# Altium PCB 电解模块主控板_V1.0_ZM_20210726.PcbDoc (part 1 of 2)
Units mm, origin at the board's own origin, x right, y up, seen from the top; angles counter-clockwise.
Board outline 150.25 x 100.26 mm, 2 copper layers (Top Layer, Bottom Layer); 209 components, 149 nets, 716 pads, 1259 vias.
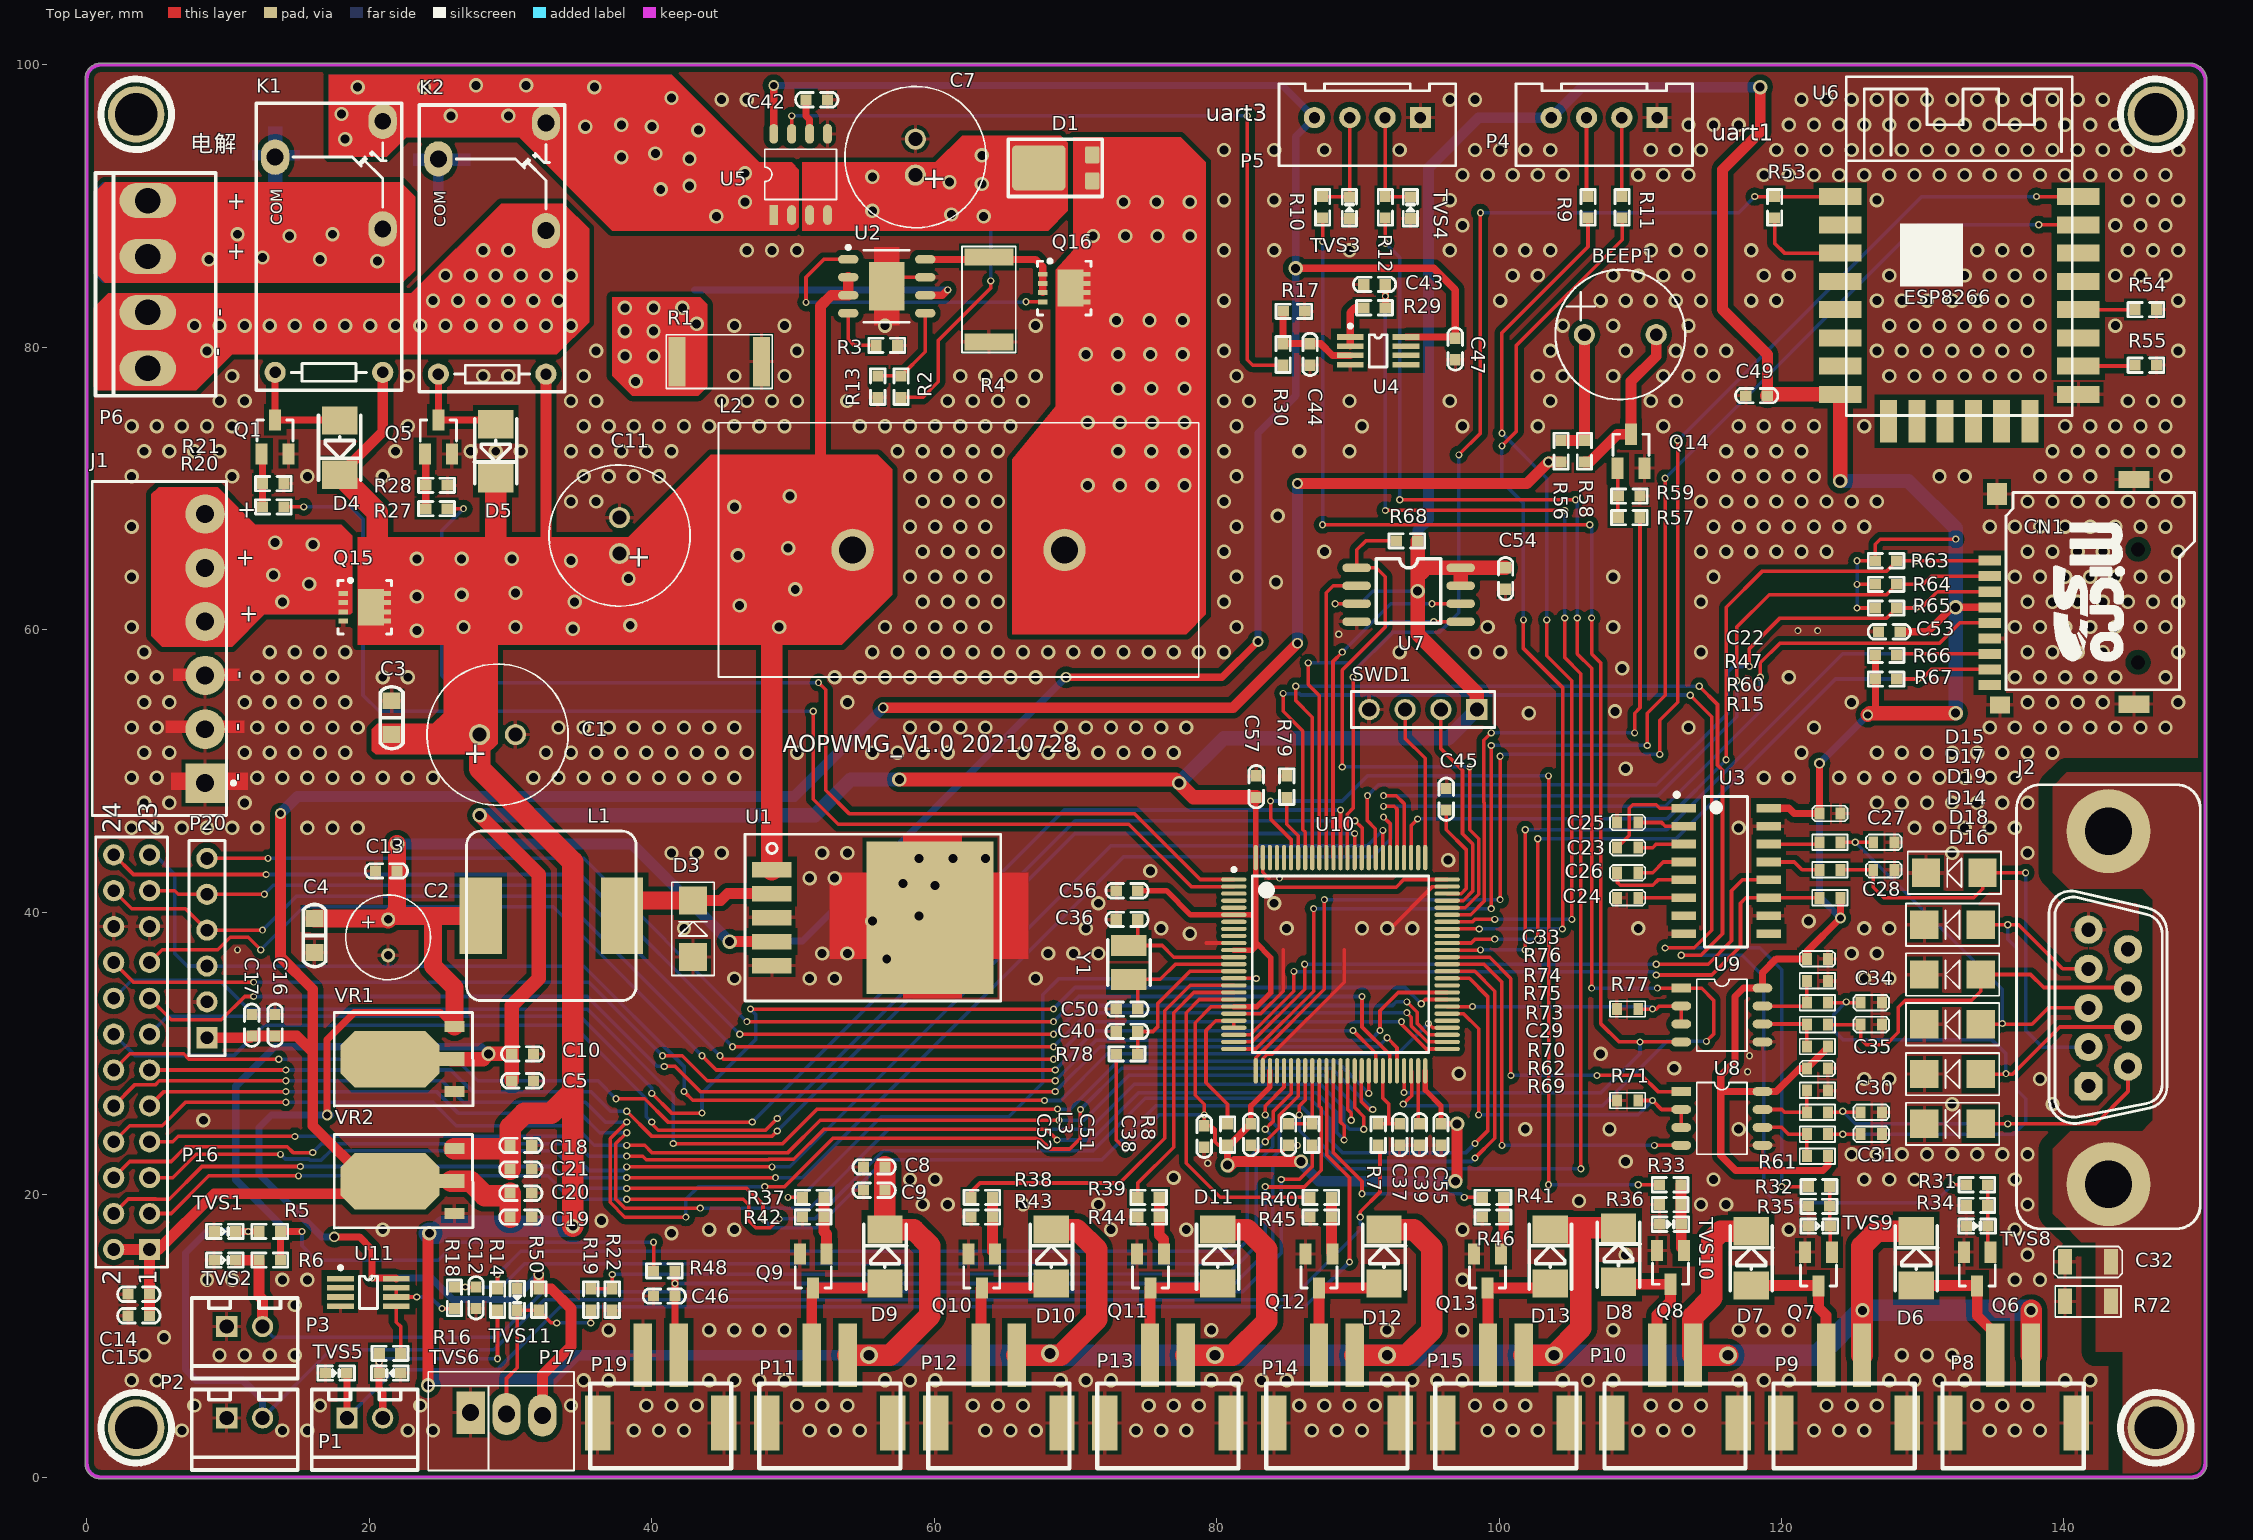
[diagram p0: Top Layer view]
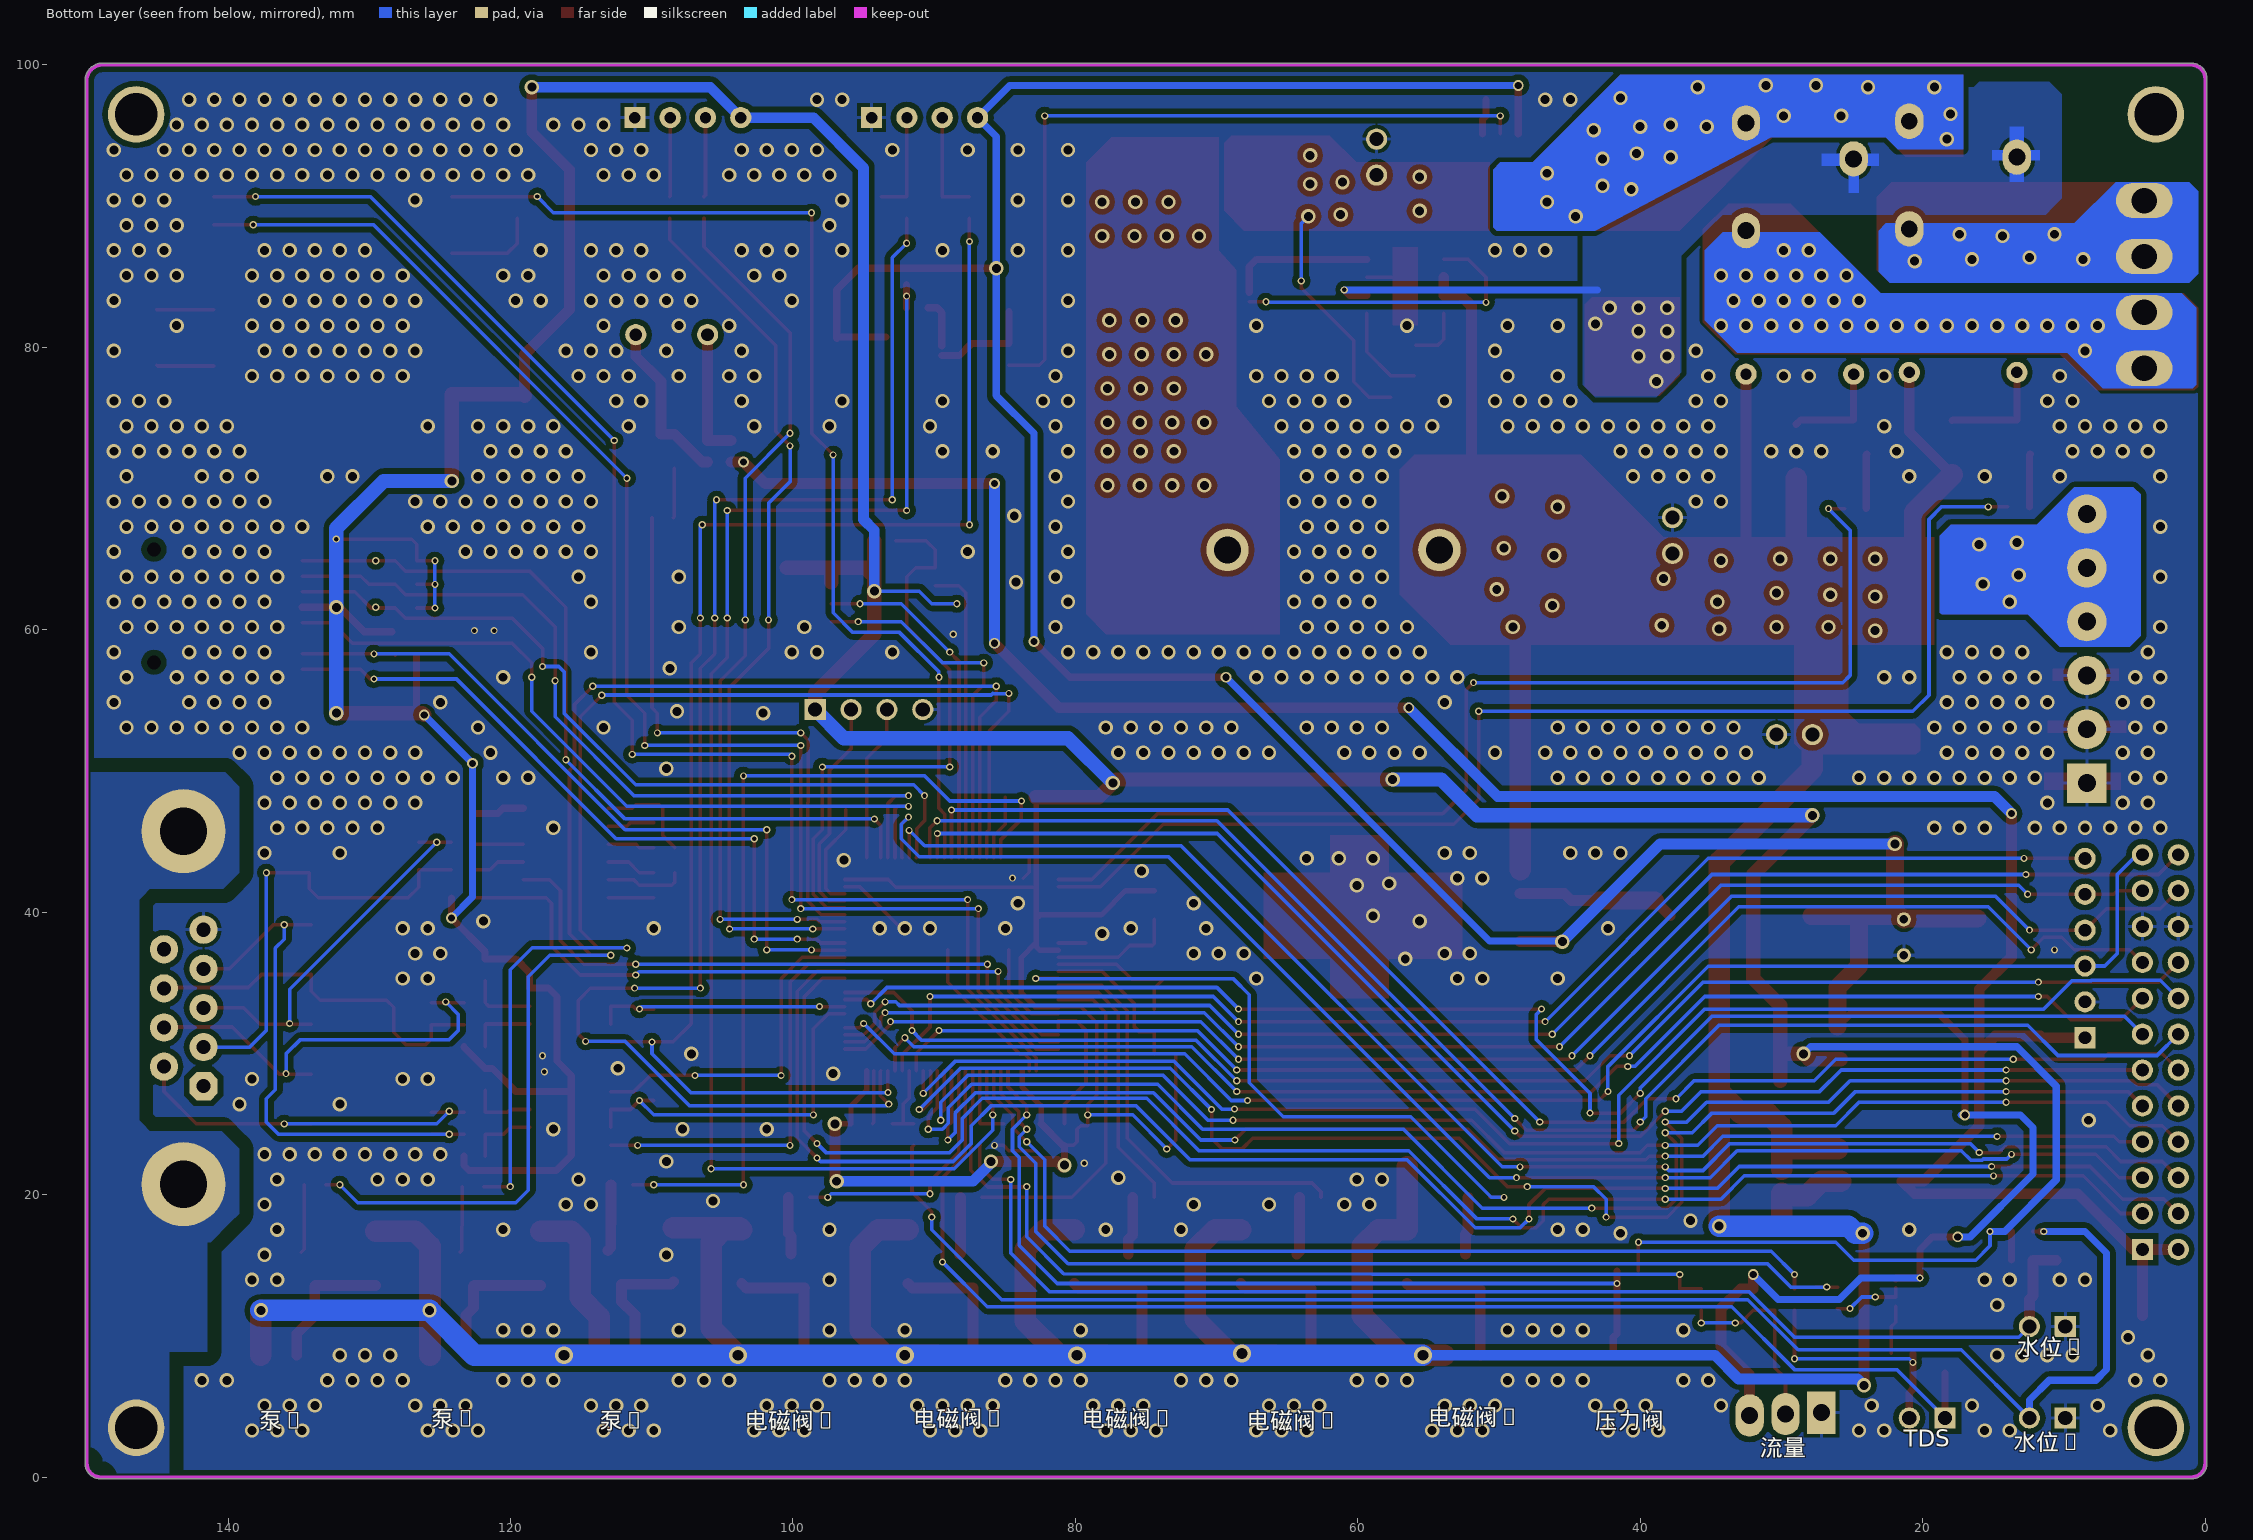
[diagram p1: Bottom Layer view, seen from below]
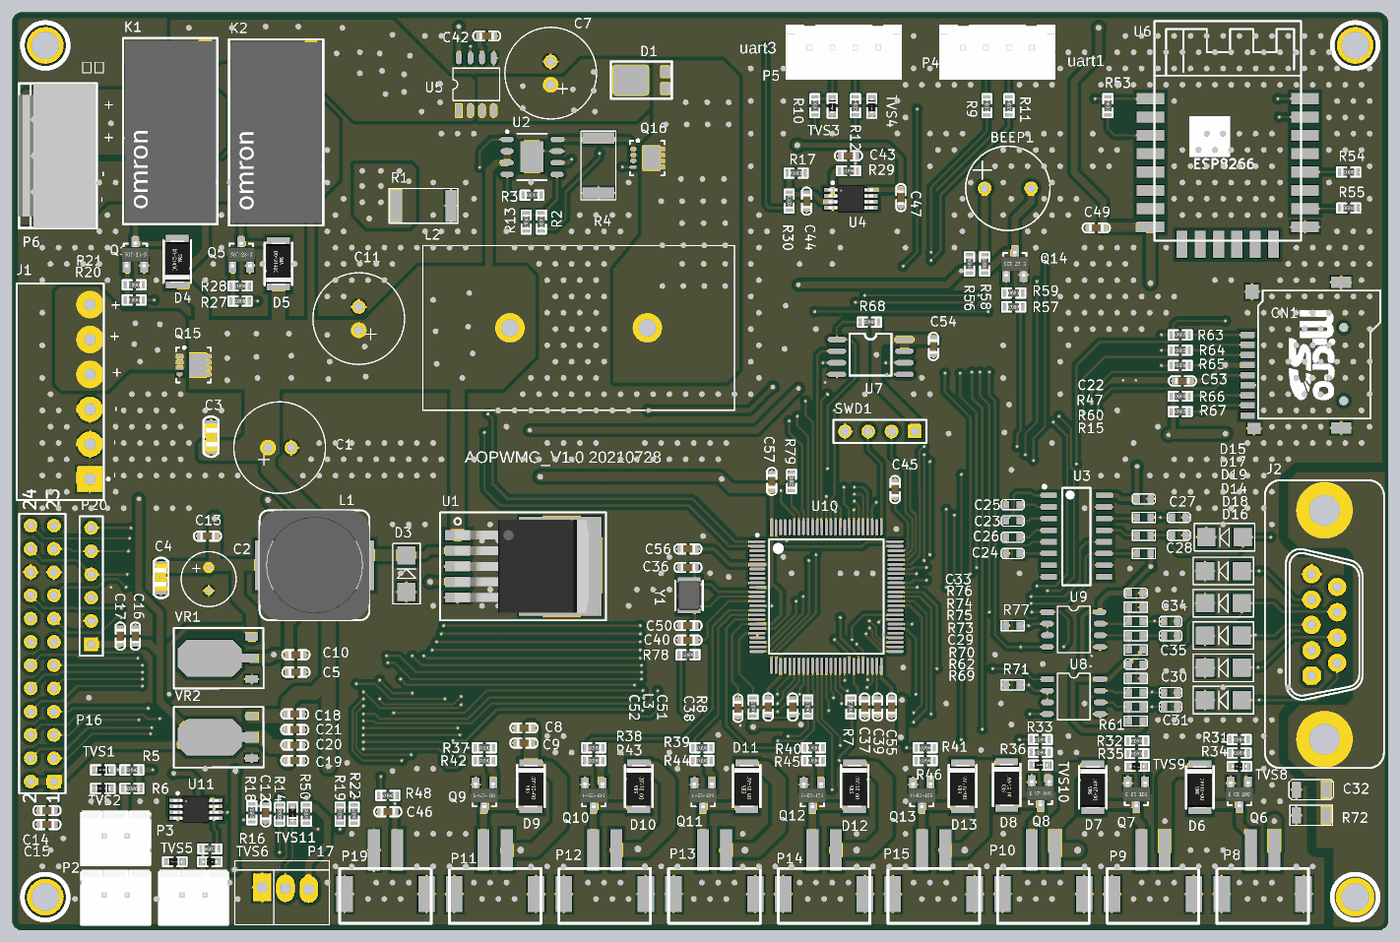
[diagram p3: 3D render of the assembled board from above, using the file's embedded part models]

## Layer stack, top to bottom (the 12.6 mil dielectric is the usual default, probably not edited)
Top Solder: solder mask 0.0102, Solder Resist, Dk 3.5
Top Layer: signal copper 0.0356
Dielectric1: dielectric 0.32, FR-4, Dk 4.8
Bottom Layer: signal copper 0.0356
Bottom Solder: solder mask 0.0102, Solder Resist, Dk 3.5

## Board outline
-0.127,1 ccw(c1,1) 1,-0.127 149,-0.127 ccw(c149,1) 150.127,1 150.127,99 ccw(c150,99) 150.126,99.016 ccw(c148.859,98.859) 148.709,100.127 1,100.127 ccw(c1,99) -0.127,99

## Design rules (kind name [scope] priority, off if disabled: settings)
Clearance Clearance_2 [InNet('NetC32_2')] p1: gap=0.152 except(1.016: Poly-Poly Poly-Region)
Clearance Clearance_1 [InPolygon] p2: gap=0.381
Clearance [All] p3: gap=0.152
NetAntennae [All] p1: netantennaetolerance=5.08
PolygonConnect PolygonConnect_2 [InNet('NetC32_2')] p1: connectstyle=Direct reliefconductorwidth=0.254 reliefentries=4 polygonreliefangle="90 Angle" airgapwidth=0.254
PolygonConnect PolygonConnect_1 [isvia] p2: connectstyle=Direct reliefconductorwidth=0.254 reliefentries=4 polygonreliefangle="90 Angle" airgapwidth=0.254
PolygonConnect [All] p3: connectstyle=Relief reliefconductorwidth=0.254 reliefentries=4 polygonreliefangle="90 Angle" airgapwidth=0.254
RoutingVias [All] p1: holewidth=0.305 width=0.61 viastyle="Through Hole" minholewidth=0.203 minwidth=0.203 maxholewidth=5.08 maxwidth=5.08
SilkToSolderMaskClearance [IsPad] p1: minsilkscreentomaskgap=0.051 clearancetoexposedcopper=TRUE
SolderMaskExpansion [All] p1: expansion=0.102
Width [All] p1: maxlimit=9.144 minlimit=0.254 preferedwidth=0.254
28 further rules are at their usual default settings.

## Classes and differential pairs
component class 02_Power: C1 C2 C3 C4 C5 C8 C9 C10 C13 C14 C15 C16 C17 C18 C19 C20 C21 D3 J1 L1 Q15 U1 VR1 VR2
component class 04_Sensor: C12 C37 C38 C47 P1 P2 P3 P17 R5 R6 R7 R8 R14 R16 R18 R19 R22 R50 TVS1 TVS2 TVS5 TVS6 TVS11 U11
component class com: C22 C23 C24 C25 C26 C27 C28 C29 C30 C31 C32 C33 C34 C35 D14 D15 D16 D17 D18 D19 J2 R15 R47 R60 R61 R62 R69 R70 R71 R72 R73 R74 R75 R76 R77 U3 U8 U9
component class 05_USART: P4 P5 R9 R10 R11 R12 TVS3 TVS4
component class cpu: C36 C39 C40 C45 C50 C51 C52 C55 C56 C57 L3 R78 R79 SWD1 U10 Y1
component class 07_EL_CON: C7 C11 C42 C43 C44 D1 D4 D5 K1 K2 L2 P6 Q1 Q5 Q16 R1 R2 R3 R4 R13 R17 R20 R21 R27 R28 R29 R30 U2 U4 U5
component class 08_Peripherals: C46 D6 D7 D8 D9 D10 D11 D12 D13 P8 P9 P10 P11 P12 P13 P14 P15 P19 Q6 Q7 Q8 Q9 Q10 Q11 Q12 Q13 R31 R32 R33 R34 R35 R36 R37 R38 R39 R40 R41 R42 R43 R44 R45 R46 R48 TVS8 TVS9 TVS10
component class 10_Wifi: C49 R53 R54 R55 U6
component class 11_Speak: BEEP1 BP1 Q14 R56 R57 R58 R59
component class 13_SPI_Flash: C54 R68 U7
component class 14_SD: C53 CN1 R63 R64 R65 R66 R67
component class 15_LCD: P16 P20

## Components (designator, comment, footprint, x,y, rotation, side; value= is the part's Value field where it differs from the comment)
BEEP1 "BEEP-9.5X5.5" BEEP-9.5X5.5 108.585,80.899 r0 top
C1 "1000uF/35V" 10*16 29.083,52.578 r180 top
C2 "100uF/35V" 6*8 21.336,38.227 r90 top
C3 "104 50V" SMD-0805C 21.59,53.778 r270 top
C4 "104 50V" SMD-0805C 16.129,38.354 r90 top
C5 "10uF 25V" SMD-0603C 30.861,28.067 r180 top
C7 "1000uF/35V" 10*16 58.674,93.472 r270 top
C8 "10uF 10V" SMD-0603C 55.753,21.971 r0 top
C9 "104 50V" SMD-0603C 55.753,20.32 r0 top
C10 "104 50V" SMD-0603C 30.861,29.972 r180 top
C11 "1000uF/35V" 10*16 37.719,66.675 r270 top
C12 "NC" SMD-0603C 27.559,12.7 r90 top
C13 "104 50V" SMD-0603C 21.209,42.926 r0 top
C14 "10uF 10V" SMD-0603C 3.683,12.954 r0 top
C15 "104 50V" SMD-0603C 3.683,11.43 r0 top
C16 "10uF 10V" SMD-0603C 13.335,32.004 r270 top
C17 "104 50V" SMD-0603C 11.684,32.004 r270 top
C18 "10uF 25V" SMD-0603C 30.734,23.495 r180 top
C19 "104 50V" SMD-0603C 30.734,18.415 r180 top
C20 "10uF 10V" SMD-0603C 30.734,20.108 r180 top
C21 "104 50V" SMD-0603C 30.734,21.802 r180 top
C22 "104 50V" 0603C 122.682,46.99 r0 top
C23 "104 50V" 0603C 108.355,44.577 r0 top
C24 "104 50V" 0603C 109.855,41.021 r180 top
C25 "104 50V" 0603C 109.855,46.355 r180 top
C26 "104 50V" 0603C 108.355,42.799 r0 top
C27 "220PF/16V" 0603C 126.492,44.958 r0 top
C28 "220PF/16V" 0603C 126.492,43.011 r0 top
C29 "104 50V" 0603C 121.793,28.942 r0 top
C30 "220PF/16V" 0603C 125.603,25.837 r0 top
C31 "220PF/16V" 0603C 125.603,24.285 r0 top
C32 "1NF/2KV" 1206C 140.081,15.24 r0 top
C33 "104 50V" 0603C 121.793,36.703 r0 top
C34 "220PF/16V" 0603C 125.603,33.599 r0 top
C35 "220PF/16V" 0603C 125.603,32.046 r0 top
C36 "12P/50V" SMD-0603C 73.66,39.497 r180 top
C37 "104 50V" SMD-0603C 92.964,24.257 r90 top
C38 "104 50V" SMD-0603C 85.09,24.257 r90 top
C39 "4.7uF/10V/NC" SMD-0603C 94.361,24.257 r90 top
C40 "1uF/10V" SMD-0603C 73.66,31.559 r0 top
C42 "104 50V" SMD-0603C 51.689,97.536 r0 top
C43 "NC" SMD-0603C 91.186,84.455 r0 top
C44 "104 50V" SMD-0603C 86.614,79.502 r270 top
C45 "4.7uF/10V/NC" SMD-0603C 96.266,48.006 r270 top
C46 "104 50V" SMD-0603C 40.894,12.827 r0 top
C47 "10uF 10V" SMD-0603C 96.901,79.883 r90 top
C49 "104 50V" SMD-0603C 118.237,76.581 r0 top
C50 "12P/50V" SMD-0603C 73.66,33.147 r180 top
C51 "104 50V" SMD-0603C 82.423,24.257 r90 top
C52 "104 50V" SMD-0603C 79.121,24.13 r90 top
C53 "104 50V" SMD-0603C 127.635,59.868 r180 top
C54 "104 50V" SMD-0603C 100.457,63.627 r270 top
C55 "104 50V" SMD-0603C 95.885,24.257 r90 top
C56 "104 50V" SMD-0603C 73.66,41.529 r0 top
C57 "104 50V" SMD-0603C 82.804,48.895 r270 top
CN1 "MicroSD Card" SD_Card_TF 134.747,64.897 r270 top
D1 "SB1545L" TO227 67.945,92.71 r90 top
D3 "SS34" SMA 42.926,36.83 r90 top
D4 "1N4007" DO-214-AC 17.907,72.898 r270 top
D5 "1N4007" DO-214-AC 28.956,72.644 r270 top
D6 "1N4007" DO-214-AC 129.54,15.494 r90 top
D7 "1N4007" DO-214-AC 117.856,15.494 r90 top
D8 "1N4007" DO-214-AC 108.458,15.748 r90 top
D9 "1N4007" DO-214-AC 56.515,15.621 r90 top
D10 "1N4007" DO-214-AC 68.294,15.621 r90 top
D11 "1N4007" DO-214-AC 80.073,15.621 r90 top
D12 "1N4007" DO-214-AC 91.853,15.621 r90 top
D13 "1N4007" DO-214-AC 103.632,15.621 r90 top
D14 "SMAJ18CA" SMA 134.112,32.067 r180 top
D15 "SMAJ18CA" SMA 134.239,42.799 r180 top
D16 "SMAJ6.5CA" SMA 134.112,25.019 r180 top
D17 "SMAJ6.5CA" SMA 134.112,39.116 r180 top
D18 "SMAJ6.5CA" SMA 134.112,28.543 r180 top
D19 "SMAJ6.5CA" SMA 134.112,35.592 r180 top
J1 "HEADER_6" DB2ERC-3P81-6P 8.382,49.149 r90 top
J2 "DB-9P-02" DIP-9 141.732,27.686 r90 top
K1 "G5Q-14-DC12" G5Q-14 17.145,87.122 r90 top
K2 "G5Q-14-DC12" G5Q-14 28.702,86.995 r90 top
L1 "33uH" CDRH-127 32.893,39.751 r180 top
L2 "33uH/15A" INDUCTOR_34*18 54.229,65.659 r0 top
L3 "MPZ1608D101BTA00" SMD-0603 80.772,24.257 r90 top
P1 "XH2.54 2P" SIP-2A 19.685,4.191 r0 top
P2 "XH2.54 2P" SIP-2A 11.176,4.191 r0 top
P3 "XH2.54 2P" SIP-2A 11.176,10.668 r0 top
P4 "1*4P" XH2.54-4A 107.442,96.266 r180 top
P5 "1*4P" XH2.54-4A 90.678,96.266 r180 top
P6 "SIP-4" VH-AW-3.96*4P 4.318,84.455 r90 top
P8 "SIP-2" XH-2.54-2P-LI 136.398,8.636 r180 top
P9 "SIP-2" XH-2.54-2P-LI 124.428,8.636 r180 top
P10 "SIP-2" XH-2.54-2P-LI 112.459,8.636 r180 top
P11 "SIP-2" XH-2.54-2P-LI 52.61,8.636 r180 top
P12 "SIP-2" XH-2.54-2P-LI 64.579,8.636 r180 top
P13 "SIP-2" XH-2.54-2P-LI 76.549,8.636 r180 top
P14 "SIP-2" XH-2.54-2P-LI 88.519,8.636 r180 top
P15 "SIP-2" XH-2.54-2P-LI 100.489,8.636 r180 top
P16 "Header 12X2" HDR2X12 4.445,16.129 r90 top
P17 "1*3P" 3X2.54MMZ2 27.178,4.572 r0 top
P19 "SIP-2" XH-2.54-2P-LI 40.64,8.636 r180 top
P20 "Header 6" HDR1X6 8.509,31.115 r90 top
Q1 "SS8050" SOT-23 13.335,73.66 r0 top
Q5 "SS8050" SOT-23 24.892,73.66 r0 top
Q6 "AO3400" SOT-23 133.858,14.732 r180 top
Q7 "AO3400" SOT-23 122.618,14.732 r180 top
Q8 "AO3400" SOT-23 112.141,14.859 r180 top
Q9 "SS8050" SOT-23 51.435,14.605 r180 top
Q10 "SS8050" SOT-23 63.373,14.605 r180 top
Q11 "SS8050" SOT-23 75.311,14.605 r180 top
Q12 "SS8050" SOT-23 87.249,14.605 r180 top
Q13 "SS8050" SOT-23 99.187,14.605 r180 top
Q14 "S8050" SOT-23 109.347,72.644 r0 top
Q15 "AON7426" DFN3*3-8 19.685,61.595 r270 top
Q16 "AON7506" DFN3*3-8 69.215,84.201 r270 top
R1 "0.03/1w" 2512R 41.783,78.994 r0 top
R2 "23K/1%" SMD-0603 57.658,77.216 r90 top
R3 "38.3K/1%" SMD-0603 56.642,80.137 r0 top
R4 "0.027/1%" 2512r 63.881,86.391 r270 top
R5 "10K" SMD-0603 12.954,17.399 r180 top
R6 "10K" SMD-0603 12.954,15.367 r180 top
R7 "10K" SMD-0603 91.44,24.257 r90 top
R8 "10K" SMD-0603 86.741,24.257 r90 top
R9 "10R" SMD-0603 106.299,89.916 r270 top
R10 "100R" SMD-0603 87.503,89.916 r270 top
R11 "10R" SMD-0603 108.712,89.916 r270 top
R12 "100R" SMD-0603 91.948,89.916 r270 top
R13 "1K/1%" SMD-0603 56.007,77.216 r270 top
R14 "510K" SMD-0603 29.083,12.573 r270 top
R15 "4.75K 1%" 0603R 124.182,41.021 r180 top
R16 "10K" SMD-0603 21.463,8.763 r0 top
R17 "10K" SMD-0603 85.471,82.55 r180 top
R18 "4.7K" SMD-0603 26.035,12.7 r270 top
R19 "10K" SMD-0603 35.687,12.573 r90 top
R20 "1K" SMD-0603 13.208,68.707 r180 top
R21 "47K" SMD-0603 13.208,70.358 r180 top
R22 "20K" SMD-0603 37.211,12.573 r90 top
R27 "1K" SMD-0603 24.765,68.58 r180 top
R28 "47K" SMD-0603 24.765,70.231 r180 top
R29 "100R" SMD-0603 91.186,82.804 r180 top
R30 "10K" SMD-0603 84.709,79.502 r270 top
R31 "100R" SMD-0603 133.833,20.701 r180 top
R32 "100R" SMD-0603 122.657,20.574 r180 top
R33 "100R" SMD-0603 112.116,20.701 r180 top
R34 "10K" SMD-0603 133.833,19.241 r180 top
R35 "10K" SMD-0603 122.657,19.177 r180 top
R36 "10K" SMD-0603 112.116,19.304 r180 top
R37 "1K" SMD-0603 51.435,19.812 r180 top
R38 "1K" SMD-0603 63.373,19.812 r180 top
R39 "1K" SMD-0603 75.184,19.812 r180 top
R40 "1K" SMD-0603 87.376,19.812 r180 top
R41 "1K" SMD-0603 99.568,19.812 r180 top
R42 "10K" SMD-0603 51.435,18.415 r180 top
R43 "10K" SMD-0603 63.373,18.415 r180 top
R44 "10K" SMD-0603 75.184,18.415 r180 top
R45 "10K" SMD-0603 87.376,18.415 r180 top
R46 "10K" SMD-0603 99.568,18.415 r180 top
R47 "22R 5%" 0603R 122.682,44.958 r0 top
R48 "10K" SMD-0603 40.894,14.605 r180 top
R50 "10K" SMD-0603 32.004,12.573 r270 top
R53 "1K" SMD-0603 119.507,89.916 r270 top
R54 "NC" SMD-0603 145.796,82.677 r180 top
R55 "1K" SMD-0603 145.796,78.74 r0 top
R56 "51R" SMD-0603 104.394,72.644 r270 top
R57 "4.7K" SMD-0603 109.22,67.945 r180 top
R58 "1K" SMD-0603 106.045,72.644 r90 top
R59 "47K" SMD-0603 109.22,69.469 r0 top
R60 "22R 5%" 0603R 122.682,43.011 r0 top
R61 "750R 5%" 0603R 121.793,22.733 r0 top
R62 "8.2R 5%" 0603R 121.793,25.837 r0 top
R63 "4.7K" SMD-0603 127.406,64.897 r0 top
R64 "4.7K" SMD-0603 127.406,63.221 r0 top
R65 "4.7K" SMD-0603 127.406,61.544 r0 top
R66 "4.7K" SMD-0603 127.406,58.191 r0 top
R67 "4.7K" SMD-0603 127.406,56.515 r0 top
R68 "4.7K" SMD-0603 93.472,66.294 r180 top
R69 "8.2R 5%" 0603R 121.793,24.285 r0 top
R70 "750R 5%" 0603R 121.793,27.39 r0 top
R71 "10K 1%" 0603R 109.855,26.67 r180 top
R72 "10M 5%" 1206r 140.081,12.446 r0 top
R73 "750R 5%" 0603R 121.793,30.494 r0 top
R74 "8.2R 5%" 0603R 121.793,33.599 r0 top
R75 "8.2R 5%" 0603R 121.793,32.046 r0 top
R76 "750R 5%" 0603R 121.793,35.151 r0 top
R77 "10K 1%" 0603R 109.855,33.147 r180 top
R78 "10K" SMD-0603 73.66,29.972 r180 top
R79 "100K" SMD-0603 84.963,48.895 r270 top
SWD1 "SIP-4 (NC)" SIP-4 94.615,54.356 r180 top
TVS1 "ESD5Z5.0T1G" SOD-523 9.779,17.399 r0 top
TVS2 "ESD5Z5.0T1G" SOD-523 9.779,15.367 r0 top
TVS3 "ESD5Z5.0T1G" SOD-523 89.408,89.891 r90 top
TVS4 "ESD5Z5.0T1G" SOD-523 93.726,89.891 r90 top
TVS5 "ESD5Z5.0T1G" SOD-523 17.653,7.366 r0 top
TVS6 "ESD5Z5.0T1G" SOD-523 21.463,7.366 r180 top
TVS8 "ESD5Z5.0T1G" SOD-523 133.858,17.78 r0 top
TVS9 "ESD5Z5.0T1G" SOD-523 122.682,17.78 r0 top
TVS10 "ESD5Z5.0T1G" SOD-523 112.141,17.907 r0 top
TVS11 "CESD5V0D1" SOD-523 30.48,12.573 r270 top
U1 "LM2596S 5.0V" TO-263-5 48.514,39.624 r270 top
U2 "OC6781" SOP127P600X265_HS-9N 56.642,84.328 r0 top
U3 "TPT3232E-SO3R" SO-16Z 113.068,47.371 r0 top
U4 "SGM358YMS/TR" MSOP-8 91.44,79.756 r0 top
U5 "ACS712ELCTR-20A-T" SO-8 48.641,89.373 r90 top
U6 "ESP-12F" ESP-12F 123.952,90.678 r0 top
U7 "W25Q128FVSIG" SO-8W 89.916,64.389 r0 top
U8 "TP8485E-SR" SO-8 112.903,27.305 r0 top
U9 "TP8485E-SR" SO-8 112.903,34.629 r0 top
U10 "GD32F405VGTx" STM-LQFP100_N 88.773,36.322 r0 top
U11 "SGM358YMS/TR" MSOP-8 19.939,13.081 r0 top
VR1 "LM1117 3.3V" SOT223 26.035,27.305 r90 top
VR2 "LM1117 5.0V" SOT223 26.035,18.669 r90 top
Y1 "8MHz" XTAL-3225-2 73.787,36.449 r90 top

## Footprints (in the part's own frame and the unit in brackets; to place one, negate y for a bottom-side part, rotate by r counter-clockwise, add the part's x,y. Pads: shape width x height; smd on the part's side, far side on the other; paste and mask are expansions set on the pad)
3X2.54MMZ2 [mm]
  rect 2x3 hole 1.2: 1(0,0)
  oval 2x3 hole 1.2: 2(2.54,-0.1) 3(5.08,-0.2)
  silkscreen extent -3,-4.1 7.31,2.9
6*8 [mm]
  round 1 hole 0.6: 1(1.27,0) 2(-1.27,0)
  silkscreen extent -3,-3 3,3
10*16 [mm]
  round 1.5 hole 1: 1(1.27,0) 2(-1.27,0)
  silkscreen extent -5,-5 5,5
0603C [mm]
  rect 0.7x0.85 smd: 1(0,0) 2(1.5,0)
  silkscreen extent -0.5,-0.55 2,0.55
0603R [mm]
  rect 0.7x0.85 smd: 1(0,0) 2(1.5,0)
  silkscreen extent -0.5,-0.55 2,0.55
1206C [mm]
  rect 1x1.8 smd: 1(0,0) 2(3.25,0)
  silkscreen extent -0.8,-1.1 4.05,1.1
1206r [mm]
  rect 1x1.8 smd: 1(0,0) 2(3.25,0)
  silkscreen extent -0.7,-1.1 3.95,1.1
2512R [mm]
  rect 1.2x3.5 smd: 1(0,0) 2(6,0)
  silkscreen extent -0.75,-1.9 6.75,1.9
2512r [mm]
  rect 1.2x3.5 smd: 1(0,0) 2(6,0)
  silkscreen extent -0.75,-1.9 6.75,1.9
BEEP-9.5X5.5 [mm]
  round 1.5 hole 0.9: 1(-2.54,0) 2(2.54,0)
  silkscreen extent -4.6,-4.6 4.6,4.6
CDRH-127 [mm]
  rect 3x5.4 smd: 1(-5,0) 2(5,0)
  silkscreen extent -6,-6 6,6, body extent -6,-6 6,6, height 8.2
DB2ERC-3P81-6P [mm]
  rect 2.79x2.79 hole 1.27: 1(0,0)
  round 2.79 hole 1.27: 2(3.81,0) 3(7.62,0) 4(11.43,0) 5(15.24,0) 6(19.05,0)
  silkscreen extent -2.3,-2.13 21.35,8
DFN3*3-8 [mm] "QFN, 16-Leads, Body 3.30x3.30mm, Pitch 0.65mm, Thermal Pad 2.45x2.45mm, IPC Medium Density"
  rect 0.35x0.65 smd: 1(0.975,-1.525) 2(-0.975,1.525) 2(-0.325,1.525) 2(0.325,1.525) 2(0.975,1.525) 3(-0.975,-1.525) 3(-0.325,-1.525) 3(0.325,-1.525)
  rect 2.6x1.84 smd: 2(0,0.45)
  silkscreen extent -2.03,-1.9 1.9,1.9, body extent -1.75,-1.75 1.75,1.75, height 0.8
DIP-9 [mm]
  oct 2x2 hole 1: 1(0,0)
  round 2 hole 1: 2(2.77,0) 3(5.54,0) 4(8.31,0) 5(11.08,0) 6(9.695,-2.803) 7(6.925,-2.803) 8(4.155,-2.803) 9(1.385,-2.803)
  round 5.95 hole 3.35: 10(-6.94,-1.42) 11(18.055,-1.42)
  silkscreen extent -10.09,-7.92 21.34,5.09
DO-214-AC [mm]
  rect 2x2.5 smd: 1(-1.915,0) 2(1.915,0)
  silkscreen extent -2.3,-1.52 2.3,1.5, body extent -2.3,-1.35 2.3,1.35, height 2.4
ESP-12F [mm]
  rect 3x1.2 smd: 1(0.203,0) 2(0.203,-2) 3(0.203,-4) 4(0.203,-6) 5(0.203,-8) 6(0.203,-10) 7(0.203,-12) 8(0.203,-14) 15(17.069,-14) 16(17.069,-12) 17(17.069,-10) 18(17.069,-8) 19(17.069,-6) 20(17.069,-4) 21(17.069,-2) 22(17.069,0)
  rect 1.2x3 smd: 9(3.632,-15.9) 10(5.632,-15.9) 11(7.632,-15.9) 12(9.632,-15.9) 13(11.632,-15.9) 14(13.632,-15.9)
  silkscreen extent 0.63,-15.49 16.64,8.49
G5Q-14 [mm]
  oval 2.5x2 hole 1.2: 1(1.27,-3.81) 2(8.89,-3.81) 3(6.35,3.81)
  round 1.5 hole 0.8: 4(-8.89,3.81) 5(-8.89,-3.81)
  silkscreen extent -10.15,-5.15 10.17,5.15, body extent -9.9,-4.95 9.9,4.95, height 15.91
HDR1X6 [mm] "Connector; Header; 6 Position"
  rect 1.5x1.5 hole 0.9: 1(0,0)
  round 1.5 hole 0.9: 2(2.54,0) 3(5.08,0) 4(7.62,0) 5(10.16,0) 6(12.7,0)
  silkscreen extent -1.27,-1.27 13.97,1.27
HDR2X12 [mm] "Connector; Header; 12x2 Position"
  rect 1.5x1.5 hole 0.9: 1(0,0)
  round 1.5 hole 0.9: 2(0,2.54) 3(2.54,0) 4(2.54,2.54) 5(5.08,0) 6(5.08,2.54) 7(7.62,0) 8(7.62,2.54) 9(10.16,0) 10(10.16,2.54) 11(12.7,0) 12(12.7,2.54) 13(15.24,0) 14(15.24,2.54) 15(17.78,0) 16(17.78,2.54) 17(20.32,0) 18(20.32,2.54) 19(22.86,0) 20(22.86,2.54) 21(25.4,0) 22(25.4,2.54) 23(27.94,0) 24(27.94,2.54)
  silkscreen extent -1.27,-1.27 29.21,3.81
INDUCTOR_34*18 [mm]
  round 3 hole 1.9: 1(0,0) 2(15,0)
  silkscreen extent -9.5,-9 24.5,9
MSOP-8 [mm]
  rect 1.9x0.4 smd: 1(-1.975,0.975) 2(-1.975,0.325) 3(-1.975,-0.325) 4(-1.975,-0.975) 5(1.975,-0.975) 6(1.975,-0.325) 7(1.975,0.325) 8(1.975,0.975)
  silkscreen extent -2.1,-1.14 0.64,1.87, body extent -2.45,-1.5 2.45,1.5, height 1.15
SD_Card_TF [mil]
  round 30 hole 39.37 mask+0: 0(-31.5,413.39) 0(283.46,413.39)
  rect 28x62 smd: 1(0,0) 2(43.31,0) 3(86.61,0) 4(129.92,0) 5(173.23,0) 6(216.54,0) 7(259.84,0) 8(303.15,0) 9(346.46,0)
  rect 48x56 smd: 10(402,28)
  rect 48x86 smd: 11(400,402) 12(-226,402)
  rect 62x56 smd: 13(-186,20)
  silkscreen extent -190,45 360,571
SIP-2A [mm]
  rect 1.5x1.5 hole 1: 1(-1.27,0)
  round 1.5 hole 1: 2(1.27,0)
  silkscreen extent -3.75,-3.68 3.75,2.02, body extent -3.7,-3.81 3.7,2.29, height 7.5
SIP-4 [mm]
  rect 1.5x1.5 hole 1: 1(-3.81,0)
  round 1.5 hole 1: 2(-1.27,0) 3(1.27,0) 4(3.81,0)
  silkscreen extent -5.08,-1.27 5.08,1.27
SMA [mm]
  rect 2x2 smd: 1(0,0) 2(4,0)
  silkscreen extent -1.3,-1.5 5.3,1.5
SMD-0603 [mil]
  rect 31.5x30 smd: 1(-30,0) 2(30,0)
  silkscreen extent -50,-20 50,20, body extent -31,-16 31,16, height 18
SMD-0603C [mil] "贴片电容"
  rect 31.5x30 smd: 1(-30,0) 2(30,0)
  silkscreen extent -59,-20 59,20, body extent -31,-16 31,16
SMD-0805C [mm]
  rect 1.2x1.27 smd: 1(-1.2,0) 2(1.2,0)
  silkscreen extent -2.2,-0.8 2.2,0.8, body extent -1.42,-0.67 1.58,0.73, height 0.93
SO-8 [mil]
  rect 55x25 smd: 1(0,0)
  oval 55x25 smd: 2(0,-50) 3(0,-100) 4(0,-150) 5(226.38,-150) 6(226.38,-100) 7(226.38,-50) 8(226.38,0)
  silkscreen extent 43,-175 183,25
SO-8W [mil]
  oval 80x24 smd: 1(0,0) 2(0,-50) 3(0,-100) 4(0,-150) 5(290,-150) 6(290,-100) 7(290,-50) 8(290,0)
  silkscreen extent 55,-155 235,25
SO-16Z [mil]
  rect 68x24 smd: 1(0,0) 2(0,-50) 3(0,-100) 4(0,-150) 5(0,-200) 6(0,-250) 7(0,-300) 8(0,-350) 9(237.11,-350) 10(237.11,-300) 11(237.11,-250) 12(237.11,-200) 13(237.11,-150) 14(237.11,-100) 15(237.11,-50) 16(237.11,0)
  silkscreen extent -19,-387 178,38
SOD-523 [mil]
  rect 31.5x30 smd: 1(-30,0) 2(30,0)
  silkscreen extent -51,-20 51,20, body extent -31,-16 31,16, height 26
SOP127P600X265_HS-9N [mm] "SOP, 8-Leads, Body 4.90x3.90mm, Pitch 1.27mm, Thermal Pad 3.40x2.52mm, IPC Medium Density"
  oval 1.45x0.6 smd: 1(-2.725,1.905) 2(-2.725,0.635) 3(-2.725,-0.635) 4(-2.725,-1.905) 5(2.725,-1.905) 6(2.725,-0.635) 7(2.725,0.635) 8(2.725,1.905)
  rect 2.52x3.4 smd: 9(0,0)
  silkscreen extent -2.85,-2.55 1.6,2.88, body extent -2,-2.55 2,2.55, height 2.65
SOT223 [mm]
  rect 0.8x1.4 smd: 1(0,0) 3(4.6,0)
  rect 1x1.854 smd: 2(2.3,0.227)
  oct 4x7 smd: 4(2.286,4.572)
  silkscreen extent -1.02,-1.3 5.59,8.51
SOT-23 [mm]
  rect 0.85x1.5 smd: 1(-0.95,-1.2) 2(0.95,-1.2) 3(0,1.2)
  silkscreen extent -1.27,-0.3 1.28,1.2, body extent -1.45,-1.4 1.45,1.4, height 1.2
STM-LQFP100_N [mm] "Thin QFP, 100-Leads, Body 14x14mm, Pitch 0.5mm, IPC Medium Density"
  oval 1.8x0.3 smd: 1(-7.55,6) 2(-7.55,5.5) 3(-7.55,5) 4(-7.55,4.5) 5(-7.55,4) 6(-7.55,3.5) 7(-7.55,3) 8(-7.55,2.5) 9(-7.55,2) 10(-7.55,1.5) 11(-7.55,1) 12(-7.55,0.5) 13(-7.55,0) 14(-7.55,-0.5) 15(-7.55,-1) 16(-7.55,-1.5) 17(-7.55,-2) 18(-7.55,-2.5) 19(-7.55,-3) 20(-7.55,-3.5) 21(-7.55,-4) 22(-7.55,-4.5) 23(-7.55,-5) 24(-7.55,-5.5) 25(-7.55,-6) 51(7.55,-6) 52(7.55,-5.5) 53(7.55,-5) 54(7.55,-4.5) 55(7.55,-4) 56(7.55,-3.5) 57(7.55,-3) 58(7.55,-2.5) 59(7.55,-2) 60(7.55,-1.5) 61(7.55,-1) 62(7.55,-0.5) 63(7.55,0) 64(7.55,0.5) 65(7.55,1) 66(7.55,1.5) 67(7.55,2) 68(7.55,2.5) 69(7.55,3) 70(7.55,3.5) 71(7.55,4) 72(7.55,4.5) 73(7.55,5) 74(7.55,5.5) 75(7.55,6)
  oval 0.3x1.8 smd: 26(-6,-7.55) 27(-5.5,-7.55) 28(-5,-7.55) 29(-4.5,-7.55) 30(-4,-7.55) 31(-3.5,-7.55) 32(-3,-7.55) 33(-2.5,-7.55) 34(-2,-7.55) 35(-1.5,-7.55) 36(-1,-7.55) 37(-0.5,-7.55) 38(0,-7.55) 39(0.5,-7.55) 40(1,-7.55) 41(1.5,-7.55) 42(2,-7.55) 43(2.5,-7.55) 44(3,-7.55) 45(3.5,-7.55) 46(4,-7.55) 47(4.5,-7.55) 48(5,-7.55) 49(5.5,-7.55) 50(6,-7.55) 76(6,7.55) 77(5.5,7.55) 78(5,7.55) 79(4.5,7.55) 80(4,7.55) 81(3.5,7.55) 82(3,7.55) 83(2.5,7.55) 84(2,7.55) 85(1.5,7.55) 86(1,7.55) 87(0.5,7.55) 88(0,7.55) 89(-0.5,7.55) 90(-1,7.55) 91(-1.5,7.55) 92(-2,7.55) 93(-2.5,7.55) 94(-3,7.55) 95(-3.5,7.55) 96(-4,7.55) 97(-4.5,7.55) 98(-5,7.55) 99(-5.5,7.55) 100(-6,7.55)
  silkscreen extent -7.67,-6.25 6.25,6.82, body extent -7,-7 7,7, height 1.6
TO227 [mm] "DPAK"
  rrect20% 1.2x1 smd: 1(-0.92,-3.25) 1(0.92,-3.25)
  rrect20% 3.2x3.8 smd: 2(0,0.533)
  silkscreen extent -2.02,-3.96 2.04,2.69
TO-263-5 [mm]
  rect 1.1x2.8 smd: 1(-3.4,0) 2(-1.7,0) 3(0,0) 4(1.7,0) 5(3.4,0)
  rect 10.8x9 smd: 6(0,11.2)
  silkscreen extent -5.9,-1.9 5.9,16.2, body extent -5.08,-0.32 5.08,14.32, height 4.57
VH-AW-3.96*4P [mm]
  oval 2.5x4 hole 1.8: 1(-5.94,0) 2(-1.98,0) 3(1.98,0) 4(5.94,0)
  silkscreen extent -7.89,-4.8 7.89,3.7, body extent -7.89,-4.7 7.89,3.8, height 11.2
XH2.54-4A [mm]
  rect 1.5x1.5 hole 0.8: 1(-3.75,0)
  round 1.5 hole 0.8: 2(-1.25,0) 3(1.25,0) 4(3.75,0)
  silkscreen extent -6.25,-2.4 6.25,3.4, body extent -6.2,-2.35 6.2,3.4, height 7.1
XH-2.54-2P-LI [mm]
  rect 1.8x3.9 smd: 0(-4.47,4.8) 0(4.47,4.8)
  rect 1.3x4.5 smd: 1(-1.27,0) 2(1.27,0)
  silkscreen extent -5,2 5,8
XTAL-3225-2 [mm]
  rect 1.5x2.5 smd: 1(-1.2,0) 2(1.2,0)
  silkscreen extent -1.6,-1.5 1.6,1.5, body extent -1.6,-1.25 1.6,1.25, height 0.9

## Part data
C1 C2 C7 C11: library part CAP2, "电解电容"
C3 C4 C8 C9 C10 C12 C13 C43 C44 C46: library part CAP4, "贴片电容 10%"
C5 C14 C15 C16 C17 C18 C19 C20 C21 C37 C38 C39 C40 C45 C49 C51 C52 C53 C54 C55 C56 C57: library part CAP4, "贴片电容 20%"
C22 C23 C24 C25 C26 C27 C28 C29 C30 C31 C32 C33 C34 C35: library part CAP
C36 C50: library part CAP4, "贴片电容 5%"
C42: library part C, "贴片电容 10%"
C47: library part "0805 22uF (226) 20% 25V", "贴片电容 10%"
CN1: library part "SD Card"
D1: library part DIODE2, "肖特基二极管"
D3: library part DIODE
D4 D5 D6 D7 D8 D9 D10 D11 D12 D13: library part DIODE2, "贴片二极管"
D14 D15 D16 D17 D18 D19: library part D_ESD
J2: library part DB9
K1 K2: library part JDQ1, "5V 继电器"
L1: library part IND
L2: library part Inductor1, "10uH 1A"
L3: library part CIZHU1, "磁珠电感 100R 100MHz"
P1 P2 P3: library part SIP-2, "XH2.54 2P 直插"
P4 P5: library part HDR1*4
P6: "3.96 4P 直插"
P8 P9 P10 P11 P12 P13 P14 P15 P19: "XH2.54 2P 立贴"
P16: "Header, 12-Pin, Dual row"
P17: library part HDR1*3
P20: "Header, 6-Pin"
Q1 Q5 Q9 Q10 Q11 Q12 Q13: library part NPN-1, "三极管"
Q6 Q7 Q8 Q15 Q16: library part "MOSFET N", "MOSFET N"
Q14: library part NPN-1, "NPN"
R1 R2 R3 R4 R13: library part R, "贴片电阻 5%"
R5 R6 R7 R8 R14 R16 R17 R30: library part RES0, "贴片电阻 1%"
R9 R10 R11 R12 R20 R21 R27 R28 R53 R54 R55 R63 R64 R65 R66 R67 R68 R78 R79: library part RES2, "贴片电阻 5%"
R15 R47 R60 R61 R62 R69 R70 R71 R72 R73 R74 R75 R76 R77: library part RES
R18 R29 R56 R57 R58 R59: library part RES0, "贴片电阻 5%"
R19 R22 R50: library part "0603 10KΩ (1002) 1%", "贴片电阻 5%"
R31 R32 R33 R34 R35 R36 R37 R38 R39 R40 R41 R42 R43 R44 R45 R46 R48: library part RES-SOP, "贴片电阻 5%"
SWD1: library part SIP-4, "ISP 下载"
TVS1 TVS2 TVS3 TVS4 TVS5 TVS6 TVS8 TVS9 TVS10: library part TVS-1, "TVS"
TVS11: library part TVS-1, "TVS 5.0V"
U1: library part LM2596
U4: library part LM358, "运算放大器"
U5: library part ACS712, "HALL 20A 电流传感器"
U6: library part ESP8266
U7: library part W25Q128FV
U10: library part STM32F405VGTx
U11: library part LM358, "运放"
VR1: library part LM1117, "三端稳压器"
VR2: library part LM1117, "三端稳压器 （耐压20V）"
Y1: library part XTAL, "3225 贴片晶振"

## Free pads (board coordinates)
  round 4 hole 3: 0(3.5,3.5) 0(3.5,96.5) 0(146.5,3.5) 0(146.5,96.5)

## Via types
v1: diameter 1.016, hole 0.635, Top Layer to Bottom Layer, tented both sides, 1001 vias
v2: diameter 0.508, hole 0.305, Top Layer to Bottom Layer, tented both sides, 238 vias
v3: diameter 0.762, hole 0.508, Top Layer to Bottom Layer, tented both sides, 14 vias
v4: diameter 1.27, hole 0.762, Top Layer to Bottom Layer, tented both sides, 6 vias

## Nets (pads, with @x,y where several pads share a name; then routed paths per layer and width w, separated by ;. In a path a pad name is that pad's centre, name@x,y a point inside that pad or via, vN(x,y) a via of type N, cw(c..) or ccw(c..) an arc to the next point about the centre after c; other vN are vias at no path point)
3.3V: C5.2 C10.2 C22.1 C29.1 C33.1 C49.2 C51.2 C52.2 C53.1 C54.1 C55.2 C56.2 C57.2 CN1.4 L3.1 P4.4 R5.1 R6.1 R15.1 R48.2 R61.2 R63.1 R64.1 R65.1 R66.1 R67.1 R68.1 R73.2 R78.2 SWD1.1 U3.16 U6.8 U7.3 U7.7 U7.8 U8.8 U9.8 U10.6 U10.11 U10.19 U10.28 U10.50 U10.75 U10.100 VR1.2 VR1.4 | length 513.8
  Top Layer w0.254: R48.2@40.132,14.605 v2(40.132,16.637) ; R78.2@72.898,29.972 72.898,23.876 v2(73.533,23.241) ; L3.1@80.772,23.495 80.137,23.495 79.883,23.749 79.883,24.638 79.629,24.892 C52.2@79.121,24.892 v2(79.121,25.654) 79.121,26.416 78.486,27.051 78.486,32.179 79.629,33.322 U10.19@81.223,33.322 ; 82.773,41.783 92.71,41.783 93.249,42.322 U10.75@96.323,42.322 ; v2(88.392,61.849) U7.3@89.916,61.849 ; v2(125.349,61.544) R65.1@126.644,61.544 ; v2(125.349,63.221) R64.1@126.644,63.221 ; v2(125.349,64.897) R63.1@126.644,64.897 126.644,66.065 127,66.421 v2(132.334,66.421)
  Top Layer w0.381: C56.2@74.422,41.529 76.454,41.529 78.161,39.822 U10.6@81.223,39.822 82.479,39.822 82.773,39.528 ; U10.19@81.223,33.322 82.852,33.322 83.82,34.29 83.82,36.799 82.773,37.846 ; U10.11@81.223,37.322 82.534,37.322 82.773,37.561 82.773,37.846 ; C51.2@82.423,25.019 82.423,26.289 83.773,27.639 U10.28@83.773,28.772 ; C57.2@82.804,48.133 82.773,48.102 U10.100@82.773,43.872 82.773,41.783 82.773,39.528 ; U10.50@94.773,28.772 94.773,27.401 95.885,26.289 C55.2@95.885,25.019 v1(97.028,25.019) ; 82.773,37.846 82.773,39.528
  Top Layer w0.508: R6.1@13.716,15.367 R5.1@13.716,17.399 v2(15.24,17.399) ; v1(80.772,22.098) L3.1@80.772,23.495 80.899,23.495 C51.2@82.423,25.019 ; U3.16@119.091,47.371 120.523,47.371 120.904,46.99 C22.1@122.682,46.99 v3(122.682,50.546) ; R61.2@123.293,22.733 123.293,22.074 122.936,21.717 116.756,21.717 115.697,22.776 115.697,27.305 ; R73.2@123.293,30.494 123.293,30.442 C29.1@121.793,28.942 121.271,28.942 119.634,27.305 U8.8@118.653,27.305 115.697,27.305 ; R15.1@124.182,41.021 v3(124.182,39.6) 121.793,37.211 C33.1@121.793,36.703 119.634,36.703 118.653,35.722 U9.8@118.653,34.629 117.306,34.629 116.713,34.036 116.713,29.462 115.697,28.446 115.697,27.305 ; v3@126.238,54.102 126.644,54.508 R67.1@126.644,56.515 R66.1@126.644,58.191 ; C53.1@128.397,59.868 130.353,59.868 132.082,61.597 CN1.4@134.747,61.597
  Top Layer w0.762: v1(80.772,22.098) 80.899,21.971 81.28,22.352 v1(85.979,22.352) ; v1(96.901,20.955) 97.028,21.082 v1(97.028,25.019) ; v1(118.491,98.425) 118.491,95.25 115.824,92.583 115.824,82.677 118.999,79.502 C49.2@118.999,76.581
  Top Layer w1.016: VR1.2@25.808,29.605 28.081,29.605 v1(28.448,29.972) C10.2@30.099,29.972 ; v1(27.813,46.863) 32.004,42.672 32.004,35.306 30.099,33.401 C10.2@30.099,29.972 ; C5.2@30.099,28.067 C10.2@30.099,29.972 ; v1(57.531,49.403) 77.089,49.403 v1(77.343,49.149) 78.359,48.133 C57.2@82.804,48.133 ; R68.1@94.234,66.294 v1(94.234,62.738) 94.234,59.69 98.425,55.499 SWD1.1@98.425,54.356 ; 94.488,64.008 94.869,64.389 U7.8@97.282,64.389 ; U7.7@97.282,63.373 U7.8@97.282,64.389 ; C54.1@100.457,64.389 U7.8@97.282,64.389 ; C49.2@118.999,76.581 119.096,76.678 U6.8@124.155,76.678 v1(124.155,70.536) ; v3(126.111,53.975) 126.238,54.102 v1(132.334,54.102)
  Bottom Layer w0.254: v2(15.24,17.399) 15.24,16.383 16.256,15.367 24.892,15.367 26.162,16.637 v2(40.132,16.637) ; v2(73.533,23.241) 75.946,25.654 v2(79.121,25.654) ; v2(88.392,61.849) 90.17,61.849 91.059,62.738 v1(94.234,62.738) ; v2(125.349,61.544) v2(125.349,63.221) v2(125.349,64.897)
  Bottom Layer w0.508: v2(15.24,17.399) 14.197,17.399 10.541,21.055 10.541,27.686 13.335,30.48 27.94,30.48 v1(28.448,29.972) ; v3(124.182,39.6) 122.682,41.1 v3(122.682,50.546) v3(126.111,53.975)
  Bottom Layer w0.762: v1@85.979,22.225 v1(85.979,22.352) ; v1@86.106,22.098 87.249,20.955 v1(96.901,20.955) ; v1(94.234,62.738) 94.234,67.056 94.996,67.818 94.996,92.71 98.552,96.266 P4.4@103.692,96.266 105.851,98.425 v1(118.491,98.425)
  Bottom Layer w1.016: v1(27.813,46.863) 51.562,46.863 54.102,49.403 v1(57.531,49.403) ; v1(77.343,49.149) 80.518,52.324 96.393,52.324 SWD1.1@98.425,54.356 ; v1(124.155,70.536) 128.981,70.536 132.334,67.183 v2(132.334,66.421) v1(132.334,61.595) v1(132.334,54.102)
ADC_ELE: C43.2 R29.1 U10.33 | length 102.1
  Top Layer w0.254: v2(85.852,25.654) 85.852,26.289 86.273,26.71 U10.33@86.273,28.772 ; v2(91.948,68.453) v2(104.648,68.453) ; v2(104.648,60.833) 104.648,58.039 105.791,56.896 v2(105.791,21.844)
  Top Layer w0.508: R29.1@91.948,82.804 v2(91.948,83.629) C43.2@91.948,84.455
  Bottom Layer w0.254: v2(85.852,25.654) 85.852,24.571 88.579,21.844 v2(105.791,21.844) ; v2(91.948,68.453) v2(91.948,83.629) ; v2(104.648,60.833) v2(104.648,68.453)
EN1_485: R71.1 U8.2 U8.3 U10.56 | length 26.1
  Top Layer w0.254: U10.56@96.323,32.822 97.48,32.822 98.552,31.75 v2(98.552,25.654) ; R71.1@109.855,26.67 v2(110.871,26.67) 111.506,26.035 U8.2@112.903,26.035 U8.3@112.903,24.765
  Bottom Layer w0.254: v2(98.552,25.654) 109.855,25.654 v2(110.871,26.67)
EN2_485: R77.1 U9.2 U9.3 U10.57 | length 19
  Top Layer w0.254: U10.57@96.323,33.322 v2(98.123,33.322) ; R77.1@109.855,33.147 v2(110.871,33.147) 111.125,33.147 111.337,33.359 U9.2@112.903,33.359 U9.3@112.903,32.089
  Bottom Layer w0.254: v2(98.123,33.322) 110.696,33.322 v2(110.871,33.147)
GND: C1.2 C2.2 C3.1 C4.1 C5.1 C7.2 C8.1 C9.1 C10.1 C11.2 C12.1 C13.1 C14.1 C15.1 C16.1 C17.1 C18.1 C19.1 C20.1 C21.1 C22.2 C24.2 C25.2 C27.2 C28.2 C29.2 C30.2 C31.2 C32.1 C33.2 C34.2 C35.2 C36.2 C37.1 C38.1 C39.1 C40.1 C42.2 C43.1 C44.2 C45.1 C46.1 C47.1 C49.1 C50.2 C51.1 C52.1 C53.2 C54.2 C55.1 C56.1 C57.1 CN1.6 CN1.10 CN1.11 CN1.12 CN1.13 D3.1 D14.2 D15.2 D16.2 D17.2 D18.2 D19.2 J1.1 J1.2 J1.3 J2.5 P2.1 P3.1 P4.1 P5.1 P8.0 P9.0 P10.0 P11.0 P12.0 P13.0 P14.0 P15.0 P16.19 P16.20 P17.1 P19.0 P19.2 P20.2 Q1.2 Q5.2 Q6.2 Q7.2 Q8.2 Q9.2 Q10.2 Q11.2 Q12.2 Q13.2 Q14.2 Q15.1 R1.2 R3.2 R4.2 R13.2 R17.1 R21.1 R22.1 R28.1 R34.2 R35.2 R36.2 R42.2 R43.2 R44.2 R45.2 R46.2 R54.1 R55.2 R59.2 R70.2 R71.2 R72.1 R76.2 R77.2 R79.1 SWD1.4 TVS1.1 TVS2.1 TVS3.1 TVS4.1 TVS5.1 TVS6.1 TVS8.1 TVS9.1 TVS10.1 TVS11.1 U1.3 U1.5 U1.6 U2.7 U2.9 U3.8 U3.10 U3.15 U4.4 U5.5 U6.15 U7.4 U8.5 U9.5 U10.10 U10.20 U10.27 U10.74 U10.99 U11.4 VR1.1 VR2.1 | length 33.3
  Top Layer w0.254: U2.9@56.642,84.328 57.277,84.963 U2.7@59.367,84.963 ; 79.272,37.822 U10.10@81.223,37.822 ; U10.20@81.223,32.822 83.114,32.822 84.709,34.417 84.709,37.338 ; 82.804,23.114 84.709,23.114 C38.1@85.09,23.495 v2(85.725,23.495) ; U10.27@83.273,28.772 83.273,29.629 83.595,29.951 83.926,29.951 89.027,35.052 89.027,37.338 ; U10.99@83.273,43.872 83.273,42.838 83.693,42.418 ; v1@92.202,38.735 95.289,41.822 U10.74@96.323,41.822
  other v1: 6.731,3.302 13.843,3.302 15.621,3.302 22.733,3.302 24.511,3.302 38.735,3.302 40.513,3.302 42.291,3.302 51.181,3.302 52.959,3.302 54.737,3.302 63.627,3.302 65.405,3.302 67.183,3.302 74.295,3.302 76.073,3.302 77.851,3.302 86.741,3.302 88.519,3.302 90.297,3.302 99.187,3.302 100.965,3.302 102.743,3.302 109.855,3.302 111.633,3.302 113.411,3.302 122.301,3.302 124.079,3.302 125.857,3.302 134.747,3.302 136.525,3.302 138.303,3.302 7.62,5.08 16.51,5.08 23.622,5.08 34.29,5.08 39.624,5.08 41.402,5.08 43.18,5.08 50.292,5.08 52.07,5.08 53.848,5.08 62.738,5.08 64.516,5.08 66.294,5.08 75.184,5.08 76.962,5.08 78.74,5.08 85.852,5.08 87.63,5.08 89.408,5.08 91.186,5.08 98.298,5.08 100.076,5.08 101.854,5.08 110.744,5.08 112.522,5.08 114.3,5.08 123.19,5.08 124.968,5.08 126.746,5.08 133.858,5.08 135.636,5.08 137.414,5.08 3.175,6.858 4.953,6.858 35.179,6.858 36.957,6.858 44.069,6.858 45.847,6.858 47.625,6.858 49.403,6.858 56.515,6.858 58.293,6.858 60.071,6.858 68.961,6.858 70.739,6.858 72.517,6.858 79.629,6.858 81.407,6.858 83.185,6.858 84.963,6.858 92.075,6.858 93.853,6.858 95.631,6.858 97.409,6.858 104.521,6.858 106.299,6.858 108.077,6.858 116.967,6.858 118.745,6.858 120.523,6.858 127.635,6.858 129.413,6.858 131.191,6.858 132.969,6.858 140.081,6.858 141.859,6.858 4.064,8.636 9.398,8.636 11.176,8.636 12.954,8.636 14.732,8.636 128.524,8.636 130.302,8.636 132.08,8.636 5.461,9.906 36.957,10.414 44.069,10.414 45.847,10.414 47.625,10.414 49.403,10.414 79.629,10.414 92.075,10.414 97.409,10.414 108.077,10.414 116.967,10.414 118.745,10.414 120.523,10.414 14.732,12.192 8.509,13.97 10.287,13.97 13.843,13.97 15.621,13.97 97.409,13.97 136.525,13.97 138.303,13.97 108.966,15.748 137.414,15.748 41.402,17.272 20.955,17.526 44.069,17.526 45.847,17.526 72.517,17.526 77.851,17.526 97.409,17.526 120.523,17.526 136.525,17.526 36.449,18.161 59.182,19.304 60.96,19.304 66.294,19.304 71.628,19.304 114.3,19.304 116.078,19.304 137.414,19.304 105.664,19.558 58.293,21.082 60.071,21.082 115.189,21.082 125.857,21.082 127.635,21.082 129.413,21.082 136.525,21.082 76.962,21.209 108.966,22.352 124.968,22.86 126.746,22.86 128.524,22.86 130.302,22.86 132.08,22.86 133.858,22.86 135.636,22.86 137.414,22.86 101.854,24.638 107.823,24.638 116.967,24.638 8.255,25.273 132.08,26.416 139.192,26.416 125.857,28.194 127.635,28.194 138.303,28.194 97.155,28.575 112.395,28.956 107.188,29.972 45.847,35.306 51.181,35.306 52.959,35.306 67.183,35.306 125.857,35.306 127.635,35.306 56.642,36.703 52.07,37.084 53.848,37.084 68.072,37.084 69.85,37.084 71.628,37.084 124.968,37.084 126.746,37.084 78.105,38.481 42.291,38.862 70.739,38.862 76.073,38.862 84.963,38.862 90.297,38.862 92.075,38.862 93.853,38.862 109.855,38.862 125.857,38.862 127.635,38.862 55.626,39.37 121.92,39.37 58.928,39.751 71.628,40.64 84.074,40.64 60.071,41.91 57.785,42.037 51.181,42.418 52.959,42.418 75.311,42.926 96.393,43.688 58.928,43.815 61.341,43.815 63.627,43.815 41.402,44.196 43.18,44.196 44.958,44.196 52.07,44.196 53.848,44.196 132.08,44.196 137.414,44.196 3.175,45.974 4.953,45.974 6.731,45.974 8.509,45.974 10.287,45.974 12.065,45.974 15.621,45.974 17.399,45.974 19.177,45.974 116.967,45.974 129.413,45.974 131.191,45.974 132.969,45.974 134.747,45.974 136.525,45.974 4.064,47.752 5.842,47.752 11.176,47.752 126.746,47.752 128.524,47.752 130.302,47.752 132.08,47.752 133.858,47.752 135.636,47.752 137.414,47.752 3.175,49.53 4.953,49.53 12.065,49.53 13.843,49.53 15.621,49.53 17.399,49.53 19.177,49.53 20.955,49.53 22.733,49.53 24.511,49.53 31.623,49.53 33.401,49.53 35.179,49.53 36.957,49.53 38.735,49.53 40.513,49.53 42.291,49.53 44.069,49.53 45.847,49.53 118.745,49.53 120.523,49.53 124.079,49.53 125.857,49.53 127.635,49.53 129.413,49.53 131.191,49.53 132.969,49.53 134.747,49.53 136.525,49.53 108.966,50.165 4.064,51.308 5.842,51.308 11.176,51.308 12.954,51.308 14.732,51.308 16.51,51.308 18.288,51.308 32.512,51.308 34.29,51.308 36.068,51.308 37.846,51.308 39.624,51.308 41.402,51.308 43.18,51.308 44.958,51.308 46.736,51.308 50.292,51.308 55.626,51.308 57.404,51.308 59.182,51.308 60.96,51.308 66.294,51.308 68.072,51.308 69.85,51.308 71.628,51.308 73.406,51.308 75.184,51.308 76.962,51.308 121.412,51.308 126.746,51.308 128.524,51.308 130.302,51.308 132.08,51.308 133.858,51.308 135.636,51.308 137.414,51.308 139.192,51.308 3.175,53.086 4.953,53.086 12.065,53.086 13.843,53.086 15.621,53.086 17.399,53.086 19.177,53.086 33.401,53.086 35.179,53.086 36.957,53.086 38.735,53.086 40.513,53.086 42.291,53.086 44.069,53.086 45.847,53.086 58.293,53.086 60.071,53.086 61.849,53.086 63.627,53.086 68.961,53.086 70.739,53.086 72.517,53.086 74.295,53.086 76.073,53.086 77.851,53.086 113.411,53.086 122.301,53.086 134.747,53.086 136.525,53.086 138.303,53.086 140.081,53.086 141.859,53.086 143.637,53.086 145.415,53.086 147.193,53.086 102.108,54.102 108.204,54.229 4.064,54.864 5.842,54.864 11.176,54.864 12.954,54.864 14.732,54.864 16.51,54.864 18.288,54.864 53.848,54.864 124.968,54.864 137.414,54.864 139.192,54.864 140.97,54.864 142.748,54.864 148.082,54.864 3.175,56.642 4.953,56.642 12.065,56.642 13.843,56.642 15.621,56.642 17.399,56.642 20.955,56.642 22.733,56.642 52.959,56.642 54.737,56.642 56.515,56.642 58.293,56.642 60.071,56.642 61.849,56.642 63.627,56.642 65.405,56.642 67.183,56.642 120.523,56.642 136.525,56.642 138.303,56.642 140.081,56.642 141.859,56.642 143.637,56.642 147.193,56.642 108.712,57.277 4.064,58.42 12.954,58.42 14.732,58.42 16.51,58.42 18.288,58.42 55.626,58.42 57.404,58.42 59.182,58.42 60.96,58.42 62.738,58.42 64.516,58.42 66.294,58.42 68.072,58.42 69.85,58.42 71.628,58.42 73.406,58.42 75.184,58.42 76.962,58.42 78.74,58.42 80.518,58.42 92.964,58.42 98.298,58.42 100.076,58.42 114.3,58.42 137.414,58.42 139.192,58.42 140.97,58.42 142.748,58.42 148.082,58.42 3.175,60.198 56.515,60.198 58.293,60.198 60.071,60.198 61.849,60.198 63.627,60.198 81.407,60.198 99.187,60.198 108.077,60.198 136.525,60.198 138.303,60.198 140.081,60.198 141.859,60.198 143.637,60.198 145.415,60.198 147.193,60.198 59.182,61.976 60.96,61.976 62.738,61.976 64.516,61.976 80.518,61.976 114.3,61.976 137.414,61.976 139.192,61.976 140.97,61.976 142.748,61.976 144.526,61.976 146.304,61.976 148.082,61.976 84.201,63.373 3.175,63.754 58.293,63.754 60.071,63.754 61.849,63.754 63.627,63.754 81.407,63.754 108.077,63.754 115.189,63.754 136.525,63.754 138.303,63.754 140.081,63.754 141.859,63.754 143.637,63.754 145.415,63.754 147.193,63.754 59.182,65.532 60.96,65.532 62.738,65.532 64.516,65.532 80.518,65.532 87.63,65.532 114.3,65.532 116.078,65.532 117.856,65.532 119.634,65.532 121.412,65.532 123.19,65.532 137.414,65.532 139.192,65.532 140.97,65.532 142.748,65.532 148.082,65.532 3.175,67.31 58.293,67.31 60.071,67.31 61.849,67.31 63.627,67.31 81.407,67.31 115.189,67.31 116.967,67.31 118.745,67.31 120.523,67.31 122.301,67.31 124.079,67.31 125.857,67.31 134.747,67.31 136.525,67.31 138.303,67.31 140.081,67.31 141.859,67.31 143.637,67.31 145.415,67.31 147.193,67.31 84.328,68.072 34.29,69.088 36.068,69.088 59.182,69.088 60.96,69.088 62.738,69.088 64.516,69.088 80.518,69.088 114.3,69.088 116.078,69.088 117.856,69.088 119.634,69.088 121.412,69.088 123.19,69.088 124.968,69.088 126.746,69.088 137.414,69.088 139.192,69.088 140.97,69.088 142.748,69.088 144.526,69.088 146.304,69.088 148.082,69.088 3.175,70.866 10.287,70.866 15.621,70.866 20.955,70.866 35.179,70.866 36.957,70.866 38.735,70.866 40.513,70.866 58.293,70.866 60.071,70.866 61.849,70.866 63.627,70.866 81.407,70.866 115.189,70.866 116.967,70.866 118.745,70.866 120.523,70.866 122.301,70.866 131.191,70.866 132.969,70.866 138.303,70.866 140.081,70.866 141.859,70.866 147.193,70.866 4.064,72.644 5.842,72.644 7.62,72.644 9.398,72.644 21.844,72.644 27.178,72.644 28.956,72.644 30.734,72.644 34.29,72.644 36.068,72.644 37.846,72.644 39.624,72.644 41.402,72.644 57.404,72.644 59.182,72.644 60.96,72.644 62.738,72.644 64.516,72.644 80.518,72.644 85.852,72.644 89.408,72.644 116.078,72.644 117.856,72.644 119.634,72.644 121.412,72.644 139.192,72.644 140.97,72.644 142.748,72.644 144.526,72.644 146.304,72.644 148.082,72.644 3.175,74.422 4.953,74.422 6.731,74.422 8.509,74.422 10.287,74.422 22.733,74.422 35.179,74.422 36.957,74.422 38.735,74.422 40.513,74.422 42.291,74.422 44.069,74.422 45.847,74.422 47.625,74.422 49.403,74.422 54.737,74.422 56.515,74.422 58.293,74.422 60.071,74.422 61.849,74.422 63.627,74.422 65.405,74.422 81.407,74.422 90.297,74.422 97.409,74.422 102.743,74.422 111.633,74.422 116.967,74.422 118.745,74.422 120.523,74.422 122.301,74.422 125.857,74.422 140.081,74.422 141.859,74.422 143.637,74.422 145.415,74.422 147.193,74.422 9.398,76.2 11.176,76.2 34.29,76.2 36.068,76.2 44.958,76.2 46.736,76.2 48.514,76.2 50.292,76.2 53.848,76.2 60.96,76.2 62.738,76.2 64.516,76.2 66.294,76.2 80.518,76.2 82.296,76.2 89.408,76.2 96.52,76.2 103.632,76.2 110.744,76.2 112.522,76.2 144.526,76.2 146.304,76.2 148.082,76.2 10.287,77.978 22.733,77.978 28.067,77.978 29.845,77.978 35.179,77.978 45.847,77.978 49.403,77.978 61.849,77.978 63.627,77.978 65.405,77.978 67.183,77.978 81.407,77.978 102.743,77.978 104.521,77.978 108.077,77.978 111.633,77.978 113.411,77.978 115.189,77.978 127.635,77.978 129.413,77.978 131.191,77.978 132.969,77.978 134.747,77.978 136.525,77.978 138.303,77.978 36.068,79.756 50.292,79.756 80.518,79.756 103.632,79.756 108.966,79.756 112.522,79.756 114.3,79.756 116.078,79.756 126.746,79.756 128.524,79.756 130.302,79.756 132.08,79.756 133.858,79.756 135.636,79.756 137.414,79.756 148.082,79.756 45.847,81.534 49.403,81.534 56.515,81.534 67.183,81.534 104.521,81.534 108.077,81.534 113.411,81.534 127.635,81.534 129.413,81.534 131.191,81.534 132.969,81.534 134.747,81.534 136.525,81.534 138.303,81.534 143.637,81.534 80.518,83.312 100.076,83.312 107.188,83.312 108.966,83.312 110.744,83.312 112.522,83.312 114.3,83.312 117.856,83.312 119.634,83.312 126.746,83.312 128.524,83.312 130.302,83.312 132.08,83.312 133.858,83.312 135.636,83.312 137.414,83.312 148.082,83.312 100.965,85.09 102.743,85.09 108.077,85.09 109.855,85.09 111.633,85.09 113.411,85.09 118.745,85.09 120.523,85.09 127.635,85.09 129.413,85.09 131.191,85.09 132.969,85.09 134.747,85.09 136.525,85.09 138.303,85.09 143.637,85.09 145.415,85.09 147.193,85.09 46.736,86.868 48.514,86.868 50.292,86.868 80.518,86.868 84.074,86.868 89.408,86.868 96.52,86.868 100.076,86.868 101.854,86.868 103.632,86.868 110.744,86.868 112.522,86.868 114.3,86.868 117.856,86.868 130.302,86.868 132.08,86.868 133.858,86.868 135.636,86.868 137.414,86.868 144.526,86.868 146.304,86.868 148.082,86.868 97.409,88.646 143.637,88.646 145.415,88.646 147.193,88.646 80.518,90.424 84.074,90.424 96.52,90.424 126.746,90.424 144.526,90.424 146.304,90.424 148.082,90.424 97.409,92.202 99.187,92.202 100.965,92.202 102.743,92.202 104.521,92.202 109.855,92.202 111.633,92.202 113.411,92.202 118.745,92.202 120.523,92.202 122.301,92.202 124.079,92.202 125.857,92.202 127.635,92.202 129.413,92.202 131.191,92.202 132.969,92.202 134.747,92.202 136.525,92.202 138.303,92.202 140.081,92.202 141.859,92.202 143.637,92.202 145.415,92.202 147.193,92.202 80.518,93.98 84.074,93.98 87.63,93.98 92.964,93.98 98.298,93.98 100.076,93.98 101.854,93.98 103.632,93.98 110.744,93.98 112.522,93.98 114.3,93.98 119.634,93.98 121.412,93.98 123.19,93.98 124.968,93.98 126.746,93.98 128.524,93.98 130.302,93.98 132.08,93.98 133.858,93.98 135.636,93.98 137.414,93.98 139.192,93.98 140.97,93.98 142.748,93.98 144.526,93.98 148.082,93.98 113.411,95.758 115.189,95.758 116.967,95.758 120.523,95.758 122.301,95.758 124.079,95.758 125.857,95.758 127.635,95.758 129.413,95.758 131.191,95.758 132.969,95.758 134.747,95.758 136.525,95.758 138.303,95.758 140.081,95.758 141.859,95.758 143.637,95.758 44.958,97.536 46.736,97.536 96.52,97.536 98.298,97.536 121.412,97.536 123.19,97.536 124.968,97.536 126.746,97.536 128.524,97.536 130.302,97.536 132.08,97.536 133.858,97.536 135.636,97.536 137.414,97.536 139.192,97.536 140.97,97.536 142.748,97.536
  other v2: 79.375,22.225 117.602,28.702 117.729,29.845 10.668,37.338 84.455,42.418 88.646,59.69 121.158,59.944 122.555,59.944
J3-2: C28.1 D15.1 J2.2 R60.2 | length 32.2
  Top Layer w0.254: R60.2@124.182,43.011 C28.1@126.492,43.011 126.492,41.783 127.254,41.021 133.604,41.021 134.239,41.656 D15.1@134.239,42.799 v2(137.287,42.799)
  Bottom Layer w0.254: v2(137.287,42.799) 137.287,31.623 138.454,30.456 J2.2@141.732,30.456
J3-3: C27.1 D14.1 J2.3 R47.2 | length 27.6
  Top Layer w0.254: R47.2@124.182,44.958 C27.1@126.492,44.958 ; D14.1@134.112,32.067 137.731,32.067 138.89,33.226 J2.3@141.732,33.226
  Bottom Layer w0.254: v2(125.222,44.958) 135.636,34.544 v2(135.636,32.131)
J3-4: C31.1 D17.1 J2.4 R69.2 | length 39
  Top Layer w0.254: R69.2@123.293,24.285 v2(124.333,24.285) C31.1@125.603,24.285 ; D17.1@134.112,39.116 v2(136.017,39.116) 136.779,39.116 139.899,35.996 J2.4@141.732,35.996
  Bottom Layer w0.254: v2(124.333,24.285) 136.426,24.285 137.287,25.146 137.287,26.797 136.652,27.432 136.652,37.465 136.017,38.1 v2(136.017,39.116)
J3-7: C35.1 D19.1 J2.7 R75.2 | length 26.6
  Top Layer w0.254: R75.2@123.293,32.046 C35.1@125.603,32.046 125.603,31.03 126.026,30.607 127.381,30.607 128.27,31.496 128.27,33.274 128.778,33.782 133.477,33.782 134.112,34.417 D19.1@134.112,35.592 137.636,35.592 138.557,34.671 144.475,34.671 J2.7@144.535,34.611
J3-8: C34.1 D18.1 J2.8 R74.2 | length 30.8
  Top Layer w0.254: R74.2@123.293,33.599 C34.1@125.603,33.599 ; D18.1@134.112,28.543 136.366,28.543 139.7,31.877 144.499,31.877 J2.8@144.535,31.841
  Bottom Layer w0.254: v2(124.587,33.655) 123.698,32.766 123.698,31.623 124.333,30.988 134.874,30.988 135.89,29.972 v2(135.89,28.575)
J3-9: C30.1 D16.1 J2.9 R62.2 | length 27.5
  Top Layer w0.254: R62.2@123.293,25.837 C30.1@125.603,25.837 ; D16.1@134.112,25.019 v2(136.017,25.019) 142.24,25.019 144.535,27.314 J2.9@144.535,29.071
  Bottom Layer w0.254: v2(124.333,25.908) 125.222,25.019 v2(136.017,25.019)
NetBEEP1_1: BEEP1.1 R56.1 R58.2 | length 9
  Top Layer w0.762: R56.1@104.394,73.406 R58.2@106.045,73.406 BEEP1.1@106.045,80.772
NetBEEP1_2: BEEP1.2 Q14.3 R58.1 | length 11.8
  Top Layer w0.762: R58.1@106.045,71.882 106.426,71.882 108.388,73.844 Q14.3@109.347,73.844 109.347,77.597 111.125,79.375 BEEP1.2@111.125,80.772
NetC12_2: C12.2 R18.1 U10.31 | length 72
  Top Layer w0.254: R18.1@26.035,13.462 v2(26.797,13.462) C12.2@27.559,13.462 ; v2(83.439,24.638) 84.023,25.222 84.023,25.908 85.273,27.158 U10.31@85.273,28.772
  Bottom Layer w0.254: v2(26.797,13.462) 29.337,13.462 30.988,15.113 80.518,15.113 82.804,17.399 82.804,22.225 83.972,23.393 83.972,24.105 v2(83.439,24.638)
NetC23_1: C23.1 U3.1 | length 7.2
  Top Layer w0.254: C23.1@108.355,44.577 109.22,45.442 109.22,47.371 109.474,47.625 111.125,47.625 111.379,47.371 U3.1@113.068,47.371
NetC23_2: C23.2 U3.3 | length 3.3
  Top Layer w0.254: C23.2@109.855,44.577 110.871,44.577 111.125,44.831 U3.3@113.068,44.831
NetC24_1: C24.1 U3.6 | length 3.2
  Top Layer w0.254: C24.1@109.855,41.021 U3.6@113.068,41.021
NetC25_1: C25.1 U3.2 | length 3.3
  Top Layer w0.254: C25.1@109.855,46.355 111.506,46.355 111.76,46.101 U3.2@113.068,46.101
NetC26_1: C26.1 U3.5 | length 5.6
  Top Layer w0.254: C26.1@108.355,42.799 108.355,42.14 108.585,41.91 110.871,41.91 111.252,42.291 U3.5@113.068,42.291
NetC26_2: C26.2 U3.4 | length 3.5
  Top Layer w0.254: C26.2@109.855,42.799 110.871,42.799 111.633,43.561 U3.4@113.068,43.561
NetC32_2: C32.2 J2.10 J2.11 pad.0@146.5,3.5 R72.2
NetC36_1: C36.1 U10.12 Y1.2 | length 8.9
  Top Layer w0.254: C36.1@74.422,39.497 74.422,37.776 74.549,37.649 76.143,37.649 76.97,36.822 U10.12@81.223,36.822
NetC37_2: C37.2 R7.2 U10.44 | length 5.5
  Top Layer w0.254: R7.2@91.44,25.019 92.202,25.019 ; U10.44@91.773,28.772 91.773,26.845 92.202,26.416 92.202,25.019 ; C37.2@92.964,25.019 92.202,25.019
NetC38_2: C38.2 R8.2 U10.34 | length 5.4
  Top Layer w0.254: C38.2@85.09,25.019 R8.2@86.741,25.019 86.773,25.051 U10.34@86.773,28.772
NetC39_2: C39.2 U10.49 | length 3.8
  Top Layer w0.254: U10.49@94.273,28.772 94.273,25.107 C39.2@94.361,25.019
NetC40_2: C40.2 R78.1 U10.14 | length 11.1
  Top Layer w0.254: R78.1@74.422,29.972 C40.2@74.422,31.559 75.501,31.559 75.819,31.877 75.819,33.528 78.113,35.822 U10.14@81.223,35.822
NetC42_1: C42.1 U5.6 | length 2.5
  Top Layer w0.508: C42.1@50.927,97.536 50.927,96.393 51.181,96.139 U5.6@51.181,95.123
NetC44_1: C44.1 R17.2 R30.1 U4.3 | length 7.4
  Top Layer w0.508: R17.2@84.709,82.55 R30.1@84.709,80.264 C44.1@86.614,80.264 87.376,80.264 88.209,79.431 U4.3@89.465,79.431
NetC45_2: C45.2 U10.73 | length 7.6
  Top Layer w0.254: C45.2@96.266,47.244 96.266,45.847 97.663,44.45 97.663,41.656 97.329,41.322 U10.73@96.323,41.322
